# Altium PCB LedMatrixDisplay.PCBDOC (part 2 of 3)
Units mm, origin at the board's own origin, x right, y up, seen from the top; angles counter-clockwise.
Board outline 305.05 x 54.1 mm, 4 copper layers (Top Layer, POWER, GROUND, Bottom Layer); 103 components, 165 nets, 805 pads, 317 vias.
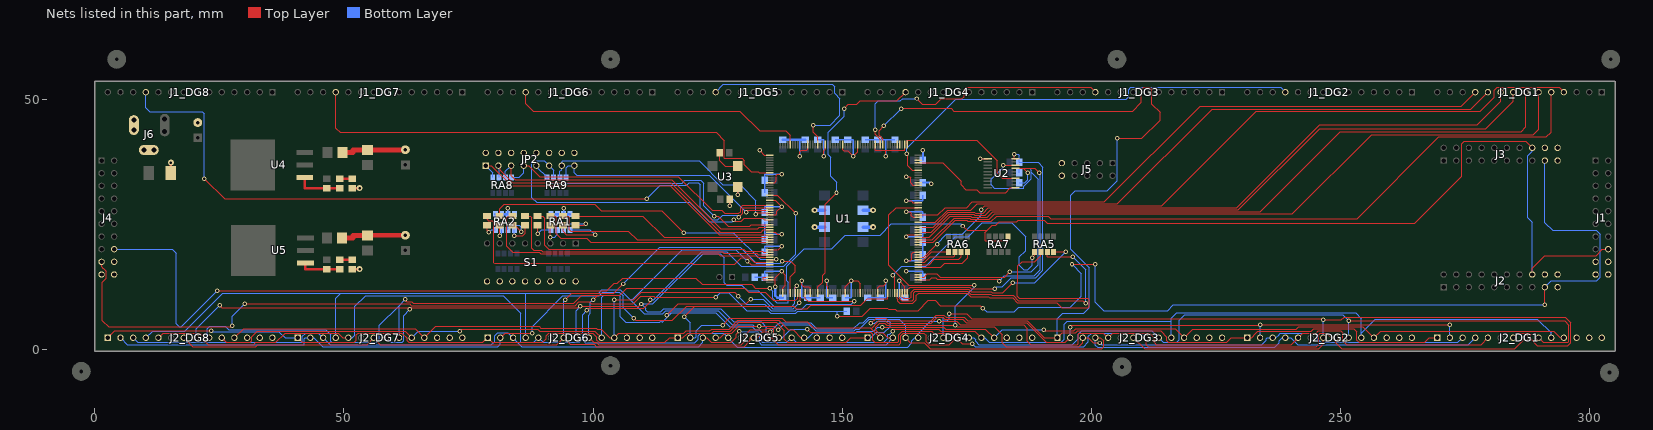
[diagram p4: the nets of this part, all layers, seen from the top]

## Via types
v1: diameter 0.9, hole 0.5, Top Layer to Bottom Layer, 307 vias
v2: diameter 1.2, hole 0.5, Top Layer to Bottom Layer, 9 vias
v3: diameter 1.27, hole 0.711, Top Layer to Bottom Layer, 1 vias

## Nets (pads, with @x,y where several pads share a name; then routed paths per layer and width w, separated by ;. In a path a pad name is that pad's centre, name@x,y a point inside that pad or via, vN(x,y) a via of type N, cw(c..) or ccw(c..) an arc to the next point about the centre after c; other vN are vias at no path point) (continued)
CNT16: J1.16 J2.16 J3.16 J4.16 RA7.1 | length 382.3
  Top Layer w0.2: v1(24.588,11.684) 102.718,11.684 104.242,13.208 104.902,13.208 105.969,14.275 120.65,14.275 121.92,13.005 131.826,13.005 132.309,12.522 132.309,12.446 132.512,12.243 v1(135.459,12.243) ; v1(174.219,24.714) 175.057,23.876 179.096,23.876 ; RA7.1@183.262,22.657 183.262,21.996 183.008,21.742 178.639,21.742 178.639,23.317 178.588,23.368 180.061,24.841 180.798,24.841 181.509,25.552 184.989,25.552 185.319,25.883 190.475,25.883 191.085,25.273 264.872,25.273 274.32,34.722 274.32,41.25 274.803,41.732 287.071,41.732 J3.16@288.417,40.386 ; J2.16@288.417,14.986 288.417,16.256 290.957,18.796 301.219,18.796 302.387,19.964 302.387,20.066 J1.16@303.657,20.066
  Bottom Layer w0.2: J4.16@3.937,20.066 15.571,20.066 16.383,19.253 16.383,5.105 16.968,4.521 17.425,4.521 v1(24.588,11.684) ; v1(135.459,12.243) 136.043,11.659 136.043,10.211 136.906,9.347 139.142,9.347 139.142,13.462 138.837,13.767 138.837,16.662 142.342,20.168 147.879,20.168 150.597,22.885 157.582,22.885 159.817,25.121 173.813,25.121 v1(174.219,24.714) ; J2.16@288.417,14.986 288.417,25.476 287.478,26.416 287.478,38.786 288.417,39.726 J3.16@288.417,40.386
CNT17: J2.17 J3.17 J4.17 R12.2 | length 382.4
  Top Layer w0.2: J4.17@1.397,17.526 1.397,16.51 1.651,16.256 1.702,16.256 2.337,15.621 2.337,14.224 1.575,13.462 1.575,5.74 2.845,4.47 27.432,4.47 v1(27.661,4.699) ; v1(30.125,9.093) 63.221,9.093 63.551,8.763 96.419,8.763 97.13,9.474 99.264,9.474 99.594,9.144 108.077,9.144 109.601,10.668 112.141,10.668 112.395,10.414 v1(124.587,10.414) ; v1(148.971,6.604) 153.999,6.604 155.65,8.255 159.073,8.255 159.327,8.001 160.655,8.001 160.909,7.747 165.227,7.747 167.259,9.779 168.656,9.779 169.672,8.763 177.673,8.763 v1(178.181,8.255) ; v1(196.088,17.018) v1(200.787,17.018) ; v1(290.957,8.89) J2.17@290.957,12.446
  Bottom Layer w0.2: v1(27.661,4.699) 27.661,6.629 v1(30.125,9.093) ; v1(124.587,10.414) 125.476,11.303 127.254,11.303 130.81,7.747 135.103,7.747 135.611,7.239 140.64,7.239 141.021,7.62 R12.2@150.942,7.62 ; v1(148.971,6.604) 148.971,7.62 ; v1(178.181,8.255) 178.943,7.493 184.531,7.493 185.42,8.382 195.707,8.382 197.993,10.668 197.993,15.113 v1(196.088,17.018) ; v1(200.787,17.018) 200.787,9.398 202.438,7.747 215.265,7.747 216.408,8.89 v1(290.957,8.89) ; J2.17@290.957,12.446 292.227,13.716 301.371,13.716 302.057,14.402 302.057,23.038 301.219,23.876 292.481,23.876 290.957,25.4 J3.17@290.957,37.846
DATA0: RA5.5 U1.99 | length 48.5
  Top Layer w0.2: v1(160.097,14.808) 160.577,14.327 U1.99@160.577,11.273 ; v1(188.113,18.351) 188.596,18.834 RA5.5@188.596,19.507
  Bottom Layer w0.2: v1(160.097,14.808) 161.951,16.662 166.726,16.662 172.67,22.606 175.286,22.606 178.08,25.4 183.961,25.4 186.767,22.594 186.767,19.768 185.497,18.498 185.497,16.815 186.411,15.9 187.212,15.9 188.113,16.801 v1(188.113,18.351)
DATA1: RA5.6 U1.100 | length 71.4
  Top Layer w0.2: U1.100@161.077,11.273 161.077,10.135 161.163,10.049 161.163,9.601 161.519,9.246 164.186,9.246 164.846,9.906 164.846,10.795 165.303,11.252 175.036,11.252 175.747,10.541 179.324,10.541 179.578,10.287 184.194,10.287 185.134,9.347 193.015,9.347 194.031,8.331 199.34,8.331 199.594,8.585 199.594,9.804 199.213,10.185 185.522,10.185 185.09,10.617 185.09,13.056 185.217,13.183 185.217,16.713 186.081,17.577 188.646,17.577 189.866,18.796 RA5.6@189.866,19.507
DATA2: RA5.7 U1.101 | length 57.6
  Top Layer w0.2: U1.101@161.577,11.273 161.577,10.084 161.933,9.728 164.008,9.728 164.338,10.058 164.338,11.303 164.687,11.652 175.202,11.652 175.805,11.049 179.8,11.049 180.054,10.795 184.252,10.795 185.293,9.754 198.247,9.754 v1(198.832,9.169) ; RA5.7@191.136,19.507 191.136,18.593 v1(196.215,18.593)
  Bottom Layer w0.2: v1(196.215,18.593) 198.832,15.977 v1(198.832,9.169)
DATA3: RA5.8 U1.102 | length 41.1
  Top Layer w0.2: U1.102@162.077,11.273 162.077,10.414 162.306,10.185 163.551,10.185 163.803,10.438 163.803,11.403 164.452,12.052 175.367,12.052 175.863,11.557 179.858,11.557 180.086,11.328 182.195,11.328 v1(184.176,13.31) ; RA5.8@192.406,19.507 v1(194.818,19.507)
  Bottom Layer w0.2: v1(184.176,13.31) 188.621,13.31 v1(194.818,19.507)
DATA4: RA6.5 U1.114 | length 6.8
  Top Layer w0.2: U1.114@165.227,17.923 166.387,17.923 167.971,19.507 RA6.5@171.324,19.507
DATA5: RA6.6 U1.113 | length 8.7
  Top Layer w0.2: U1.113@165.227,17.423 166.522,17.423 167.64,18.542 172.391,18.542 172.594,18.745 RA6.6@172.594,19.507
DATA6: RA6.7 U1.112 | length 10.3
  Top Layer w0.2: U1.112@165.227,16.923 167.412,16.923 168.497,18.009 173.33,18.009 173.864,18.542 RA6.7@173.864,19.507
DATA7: RA6.8 U1.111 | length 11.9
  Top Layer w0.2: U1.111@165.227,16.423 169.749,16.423 170.597,17.272 174.067,17.272 175.134,18.339 RA6.8@175.134,19.507
DIN: U1.153 U2.1 | length 22.8
  Top Layer w0.2: U1.153@165.227,37.423 170.12,37.423 173.845,33.699 173.845,32.969 174.785,32.029 177.013,32.029 177.623,31.42 182.753,31.42 183.711,32.377 U2.1@184.758,32.377
DONE: R4.2 U1.104 U2.10 | length 59.2
  Top Layer w0.2: U1.104@163.077,11.273 163.077,11.938 163.592,12.452 175.533,12.452 175.895,12.09 v1(180.62,12.09) ; v1(184.481,39.065) 184.481,38.227 U2.10@184.758,38.227
  Bottom Layer w0.2: v1(180.62,12.09) 181.026,12.497 182.068,12.497 183.896,14.326 188.773,14.326 190.246,15.799 190.246,36.525 189.307,37.465 R4.2@185.481,37.465 185.481,38.862 185.278,39.065 v1(184.481,39.065)
ENABLE0: J1_DG1.11 U1.132 | length 122
  Top Layer w0.2: U1.132@165.227,26.923 169.164,26.923 170.638,28.397 174.93,28.397 176.073,29.54 202.565,29.54 221.793,48.768 274.193,48.768 J1_DG1.11@276.987,51.562
ENABLE1: J1_DG2.11 U1.150 | length 88.3
  Top Layer w0.2: v1(162.941,39.218) 163.17,38.989 163.17,36.805 164.051,35.923 U1.150@165.227,35.923
  Bottom Layer w0.2: v1(162.941,39.218) 162.941,40.335 172.797,50.19 207.01,50.19 207.468,50.648 207.468,52.07 207.899,52.502 237.948,52.502 J1_DG2.11@238.887,51.562
ENABLE2: J1_DG3.11 U1.168 | length 56.3
  Top Layer w0.2: v1(156.591,44.018) 156.591,43.15 157.577,42.164 U1.168@157.577,41.073 ; v1(164.897,50.292) 166.091,49.098 168.733,49.098 169.85,50.216 174.016,50.216 174.448,50.648 174.448,52.07 174.879,52.502 199.848,52.502 J1_DG3.11@200.787,51.562
  Bottom Layer w0.2: v1(156.591,44.018) 156.591,49.251 157.201,49.86 161.671,49.86 162.103,50.292 v1(164.897,50.292)
ENABLE3: J1_DG4.11 U1.68 | length 54.2
  Top Layer w0.2: U1.68@145.077,11.273 145.077,12.489 146.05,13.462 146.05,14.859 146.558,15.367 146.558,29.083 v1(148.844,31.369) ; v1(150.368,48.26) 151.206,49.098 152.908,49.098 153.645,49.835 160.96,49.835 J1_DG4.11@162.687,51.562
  Bottom Layer w0.2: v1(148.844,31.369) 148.844,33.528 147.701,34.671 147.701,38.481 147.193,38.989 147.193,43.561 150.368,46.736 v1(150.368,48.26)
ENABLE4: J1_DG5.11 U1.193 | length 41.3
  Top Layer w0.2: v1(144.145,44.958) 144.145,43.561 145.077,42.629 U1.193@145.077,41.073
  Bottom Layer w0.2: J1_DG5.11@124.587,51.562 126.137,53.111 148.006,53.111 148.463,52.654 148.463,51.308 149.505,50.267 149.505,46.889 147.574,44.958 v1(144.145,44.958)
ENABLE5: J1_DG6.11 U1.204 | length 59.9
  Top Layer w0.2: J1_DG6.11@86.487,51.562 86.487,49.225 87.961,47.752 129.464,47.752 133.408,43.808 138.695,43.808 139.577,42.926 U1.204@139.577,41.073
ENABLE6: J1_DG7.11 U1.8 | length 100.5
  Top Layer w0.2: J1_DG7.11@48.387,51.562 48.387,44.348 49.251,43.485 124.74,43.485 126.365,41.859 126.365,38.303 129.896,38.303 130.353,37.846 130.353,37.008 131.75,35.611 133.188,35.611 133.376,35.423 U1.8@135.427,35.423
ENABLE7: J1_DG8.11 U1.22 | length 152.5
  Top Layer w0.2: v1(22.022,34.214) 26.086,30.15 110.77,30.15 v1(110.821,30.201) ; v1(129.236,26.467) 129.998,27.229 129.998,28.27 130.151,28.423 U1.22@135.427,28.423
  Bottom Layer w0.2: J1_DG8.11@10.287,51.562 10.287,48.412 11.1,47.6 21.616,47.6 22.022,47.193 v1(22.022,34.214) ; v1(110.821,30.201) 113.462,32.842 118.771,32.842 119.304,33.376 121.108,33.376 121.514,32.969 121.514,28.372 123.952,25.933 125.07,25.933 125.984,26.848 128.855,26.848 v1(129.236,26.467)
FPGA_C\S\: U1.160
FPGA_D1: U1.145
FPGA_D4: U1.126
FPGA_D5: U1.120
FPGA_D6: U1.116
FPGA_D7: U1.108
"FPGA_DOUT_ BUSY": U1.154
FPGA_TDO-TDI: U1.157 U2.4 | length 27.2
  Top Layer w0.2: U1.157@163.077,41.073 163.077,41.961 176.962,41.961 181.077,37.846 181.077,35.394 182.144,34.327 U2.4@184.758,34.327
FPGA_W\R\I\T\E\: U1.161
GND: C1.2 C2.2 C3.2 C4.2 C5.1 C6.1 C7.1 C8.1 C9.1 C10.1 C11.1 C12.1 C13.1 C14.1 C15.1 C16.1 C17.1 C18.1 C19.2 C20.2 C21.2 C22.2 C23.2 C24.2 C25.2 C26.2 C27.2 C28.2 C29.2 C30.2 C31.2 C32.2 C34.1 C35.1 C36.1 C37.2 C38.2 C39.2 C40.2 C41.2 C42.2 C43.2 C44.2 D1.1 J1.17 J1.18 J1.19 J1.20 J2.18 J2.19 J2.20 J2_DG1.12 J2_DG1.13 J2_DG1.14 J2_DG2.12 J2_DG2.13 J2_DG2.14 J2_DG3.12 J2_DG3.13 J2_DG3.14 J2_DG4.12 J2_DG4.13 J2_DG4.14 J2_DG5.12 J2_DG5.13 J2_DG5.14 J2_DG6.12 J2_DG6.13 J2_DG6.14 J2_DG7.12 J2_DG7.13 J2_DG7.14 J2_DG8.12 J2_DG8.13 J2_DG8.14 J3.18 J3.19 J3.20 J4.18 J4.19 J4.20 J5.9 J5.10 J6.2 J6.2A J6.2B J6.3 J6.3A J6.3B JP2.2 JP2.4 JP2.6 JP2.8 JP2.10 JP2.12 JP2.14 JP2.16 R1.1 R9.1 R11.2 RA1.5 RA1.6 RA1.7 RA1.8 RA2.5 RA2.6 RA2.7 RA2.8 S1.9 S1.10 S1.11 S1.12 S1.13 S1.14 S1.15 S1.16 U1.1 U1.12 U1.19 U1.25 U1.32 U1.39 U1.50 U1.51 U1.54 U1.65 U1.72 U1.79 U1.85 U1.92 U1.103 U1.117 U1.124 U1.131 U1.137 U1.144 U1.158 U1.170 U1.177 U1.183 U1.190 U1.197 U2.11 U3.2 | length 260.8
  Top Layer w0.2: v1(133.411,39.878) 134.366,38.923 U1.1@135.427,38.923 ; U1.50@135.427,14.423 134.112,14.423 134.112,13.923 U1.51@135.427,13.923 136.479,13.923 136.602,14.046 ; U1.39@135.427,19.923 137.158,19.923 v1(137.84,20.606) ; U1.32@135.427,23.423 136.597,23.423 136.914,23.106 v1(137.84,23.106) ; U1.25@135.427,26.923 136.652,26.923 136.906,27.178 136.906,27.672 v1(137.84,28.606) 136.523,29.923 U1.19@135.427,29.923 ; U1.12@135.427,33.423 136.421,33.423 136.779,33.782 136.779,34.925 136.96,35.106 v1(137.84,35.106) ; v1(136.602,12.497) 136.602,14.046 ; 137.5,15.265 136.602,14.367 136.602,14.046 ; v1(137.84,15.606) 138.608,14.838 138.608,12.802 138.077,12.271 U1.54@138.077,11.273 ; v1(141.439,38.674) 141.439,39.584 141.732,39.878 142.875,39.878 143.077,40.08 U1.197@143.077,41.073 ; v1(141.895,13.686) 141.895,12.919 142.24,12.573 143.383,12.573 143.577,12.379 U1.65@143.577,11.273 ; v1(146.26,38.66) 146.26,39.834 146.577,40.151 U1.190@146.577,41.073 ; v1(146.895,13.686) 146.895,12.745 147.077,12.562 U1.72@147.077,11.273 ; U1.183@150.077,41.073 150.077,40.042 150.338,39.781 151.079,39.781 v1(152.186,38.674) 153.077,39.565 U1.177@153.077,41.073 ; U1.79@150.577,11.273 150.577,12.504 v1(151.76,13.686) 153.065,13.686 153.577,13.174 U1.85@153.577,11.273 ; U1.170@156.577,41.073 156.577,39.878 158.75,39.878 ; U1.92@157.077,11.273 157.077,12.297 157.48,12.7 158.369,12.7 158.75,13.081 v1(158.75,13.718) ; v1(158.75,38.66) 158.75,39.878 ; v1(161.395,13.686) 162.577,12.504 U1.103@162.577,11.273 ; U1.158@162.577,41.073 162.577,39.878 158.75,39.878 ; v1(162.814,17.741) 163.664,17.741 163.957,18.034 163.957,19.177 164.204,19.423 U1.117@165.227,19.423 ; v1(162.814,22.606) 163.132,22.923 U1.124@165.227,22.923 ; v1(162.814,27.606) 163.529,27.606 163.83,27.305 163.83,26.797 164.204,26.423 U1.131@165.227,26.423 ; v1(162.814,29.741) 163.808,29.741 164.125,29.423 U1.137@165.227,29.423 ; v1(162.814,34.606) 163.514,34.606 163.703,34.417 163.703,33.401 164.181,32.923 U1.144@165.227,32.923 ; v1(177.673,38.227) U2.11@179.208,38.227
  Top Layer w0.3: v1(127.442,28.772) C37.2@127.442,30.099 ; v1(129.032,30.954) U3.2@129.032,32.531
  Top Layer w0.5: D1.1@15.304,35.306 v2(15.304,37.43) ; R11.2@51.689,16.068 v2(53.166,16.068) ; R9.1@51.689,32.324 v2(53.166,32.324) ; C42.2@62.206,40.005 C42.2@62.23,39.981 ; C44.2@62.357,22.812 C44.2@62.357,22.86
  Top Layer w1: C40.2@49.609,22.352 51.816,22.352 51.816,22.812 C41.2@54.737,22.812 54.737,22.86 C44.2@62.357,22.86 ; C38.2@49.76,39.497 51.816,39.497 51.816,39.957 C39.2@54.737,39.957 62.357,39.957 C42.2@62.357,40.005
  Bottom Layer w0.254: RA2.7@82.931,27.102 v1(82.931,28.279) ; RA1.7@94.107,27.102 v1(94.107,28.279)
  Bottom Layer w0.3: R1.1@132.445,14.423 C34.1@134.477,14.423 134.477,15.606 v1(137.84,15.606) ; C22.2@134.477,19.423 134.477,20.606 v1(137.84,20.606) ; C29.2@134.477,21.923 134.477,23.106 v1(137.84,23.106) ; C28.2@134.477,25.423 134.493,23.114 ; C21.2@134.477,27.423 134.477,28.606 v1(137.84,28.606) ; C27.2@134.477,31.423 C20.2@134.477,33.923 134.477,35.106 v1(137.84,35.106) ; v1(141.439,38.674) 141.439,42.023 ; v1(141.895,13.686) 141.895,10.323 C25.2@143.077,10.323 C32.2@145.577,10.323 ; C7.1@142.577,42.037 C7.1@142.621,42.037 ; C15.1@145.077,42.023 146.26,42.023 v1(146.26,38.66) ; v1(146.895,13.686) 146.895,10.323 C35.1@148.077,10.323 ; C14.1@148.577,42.023 C6.1@151.077,42.023 ; C24.2@150.577,10.323 151.76,10.323 v1(151.76,13.686) ; C6.1@151.003,42.037 151.077,42.037 152.186,42.037 v1(152.186,38.674) ; C13.1@154.577,42.023 C5.1@157.077,42.023 158.75,42.023 ; C31.2@155.077,10.323 C23.2@157.577,10.323 157.567,10.355 157.577,10.355 158.75,10.355 v1(158.75,13.718) ; v1(158.75,38.66) 158.75,42.023 ; C9.1@160.577,42.023 158.75,42.023 ; v1(161.395,13.686) 161.395,10.323 C36.1@162.577,10.323 ; v1(162.814,15.606) 166.177,15.606 C19.2@166.177,14.423 ; v1(162.814,17.741) 166.177,17.741 C12.1@166.177,18.923 C18.1@166.177,21.423 ; v1(162.814,22.606) 166.177,22.606 C17.1@166.177,23.923 ; v1(162.814,27.606) 166.177,27.606 C11.1@166.177,26.423 ; v1(162.814,29.741) 166.177,29.741 C16.1@166.177,30.923
  Bottom Layer w0.4: C10.1@166.177,33.423 167.618,33.423 v1(167.894,33.147) ; C30.2@166.177,37.923 v1(166.177,39.878)
  Bottom Layer w0.5: RA2.5@80.391,27.102 RA2.6@81.661,27.102 RA2.7@82.931,27.102 RA2.8@84.201,27.102 ; RA1.5@91.567,27.102 RA1.6@92.837,27.102 RA1.7@94.107,27.102 RA1.8@95.377,27.102 ; v1(136.602,12.497) 136.602,10.718 136.997,10.323 C26.2@138.077,10.323 ; C8.1@138.077,42.023 141.439,42.023 C7.1@142.577,42.023
  Bottom Layer w0.7: v2(144.444,24.473) C3.2@146.477,24.473 ; v2(144.444,27.873) C2.2@146.477,27.873 ; C4.2@154.177,24.473 v2(156.21,24.473) ; C1.2@154.177,27.873 v2(156.21,27.873)
GREEN0: J2_DG1.1 J2_DG2.1 J2_DG3.1 J2_DG4.1 J2_DG5.1 J2_DG6.1 J2_DG7.1 J2_DG8.1 U1.167 | length 431.6
  Top Layer w0.2: J2_DG8.1@2.667,2.286 4.039,3.658 v1(23.419,3.658) ; J2_DG7.1@40.767,2.286 41.707,1.346 52.096,1.346 52.528,1.778 52.528,2.896 52.858,3.226 61.646,3.226 62.688,2.184 62.688,1.676 63.018,1.346 77.928,1.346 J2_DG6.1@78.867,2.286 79.807,1.346 89.891,1.346 90.628,2.083 90.628,2.743 91.11,3.226 99.949,3.226 100.788,2.388 100.788,1.829 101.27,1.346 114.427,1.346 115.367,2.286 J2_DG5.1@116.967,2.286 118.034,2.286 118.974,3.226 123.851,3.226 124.257,3.632 127.508,3.632 129.25,5.373 136.74,5.373 138.405,3.708 138.405,2.007 139.065,1.346 150.8,1.346 151.74,2.286 J2_DG4.1@155.067,2.286 ; v1(155.728,5.182) 156.769,6.223 158.75,6.223 159.258,5.715 167.811,5.715 168.903,6.807 170.383,6.807 170.815,6.375 174.473,6.375 175.159,5.69 187.154,5.69 190.558,2.286 J2_DG3.1@193.167,2.286 194.158,3.277 196.876,3.277 197.257,3.658 213.843,3.658 215.088,2.413 215.088,1.676 215.418,1.346 227.127,1.346 228.067,2.286 J2_DG2.1@231.267,2.286 232.131,2.286 232.537,2.692 232.537,2.819 233.35,3.632 244.094,3.632 244.552,4.089 252.629,4.089 253.188,3.531 253.188,1.829 253.67,1.346 266.827,1.346 267.767,2.286 J2_DG1.1@269.367,2.286 ; U1.167@158.077,41.073 158.077,42.266 157.404,42.939 157.404,43.815 v1(158.369,44.78) ; v1(161.798,48.209) 161.882,48.292 171.817,48.292 172.358,47.752 208.23,47.752 210.008,49.53 210.008,52.07 210.439,52.502 211.659,52.502 212.09,52.07 212.09,49.174 213.741,47.523 213.741,45.974 210.084,42.316 v1(205.156,42.316)
  Bottom Layer w0.2: v1(23.419,3.658) 23.546,3.531 36.983,3.531 38.227,2.286 J2_DG7.1@40.767,2.286 ; J2_DG4.1@155.067,2.286 155.728,2.286 156.795,3.353 158.471,3.353 159.639,4.521 159.639,5.334 159.385,5.588 156.972,5.588 156.566,5.182 v1(155.728,5.182) ; v1(158.369,44.78) v1(161.798,48.209) ; J2_DG3.1@193.167,2.286 193.167,6.147 194.183,7.163 198.4,7.163 199.594,8.357 199.594,16.358 195.86,20.091 195.86,30.836 196.774,31.75 203.124,31.75 205.156,33.782 v1(205.156,42.316)
GREEN1: J2_DG1.2 J2_DG2.2 J2_DG3.2 J2_DG4.2 J2_DG5.2 J2_DG6.2 J2_DG7.2 J2_DG8.2 U1.96 | length 346.9
  Top Layer w0.2: J2_DG6.2@81.407,2.286 82.347,3.226 v1(87.783,3.226) ; v1(108.128,6.172) 108.535,5.766 115.926,5.766 118.771,8.611 140.234,8.611 140.767,8.077 143.002,8.077 143.714,8.788 153.695,8.788 155.013,10.106 159.077,10.106 U1.96@159.077,11.273 ; v1(118.314,6.502) 120.422,8.611 ; v1(125.984,4.801) 127.357,6.173 137.999,6.173 138.686,5.486 143.002,5.486 144.221,4.267 155.626,4.267 J2_DG4.2@157.607,2.286 ; 155.769,4.124 155.769,4.131 157.353,5.715 158.623,5.715 159.112,5.226 167.888,5.226 169.037,6.375 170.155,6.375 170.561,5.969 174.219,5.969 174.905,5.283 186.97,5.283 190.907,1.346 194.768,1.346 J2_DG3.2@195.707,2.286 ; v1(195.707,4.445) 196.114,4.851 233.757,4.851 v1(233.807,4.902) v1(271.907,4.902)
  Bottom Layer w0.2: J2_DG8.2@5.207,2.286 6.554,0.94 42.114,0.94 42.114,2.083 42.317,2.286 J2_DG7.2@43.307,2.286 43.968,2.286 45.771,0.483 80.874,0.483 81.407,1.016 J2_DG6.2@81.407,2.286 ; v1(87.783,3.226) 87.783,4.521 93.955,10.693 101.244,10.693 101.981,11.43 105.283,11.43 106.02,10.693 106.02,8.28 v1(108.128,6.172) ; v1(118.314,6.502) 119.507,5.309 J2_DG5.2@119.507,2.286 120.473,2.286 120.676,2.489 120.676,3.708 121.768,4.801 v1(125.984,4.801) ; J2_DG3.2@195.707,2.286 v1(195.707,4.445) ; J2_DG2.2@233.807,2.286 v1(233.807,4.902) ; J2_DG1.2@271.907,2.286 v1(271.907,4.902)
GREEN2: J2_DG1.3 J2_DG2.3 J2_DG3.3 J2_DG4.3 J2_DG5.3 J2_DG6.3 J2_DG7.3 J2_DG8.3 U1.135 | length 339.2
  Top Layer w0.2: J2_DG5.3@122.047,2.286 122.809,2.286 123.749,1.346 127.686,1.346 128.728,2.388 128.728,2.997 v1(129.286,3.556) ; J2_DG4.3@160.147,2.286 159.131,2.286 158.115,3.302 157.226,3.302 156.718,3.81 156.718,4.445 157.48,5.207 158.496,5.207 158.877,4.826 172.619,4.826 172.974,4.47 180.518,4.47 182.068,2.921 182.068,1.27 182.88,0.457 197.435,0.457 198.247,1.27 J2_DG3.3@198.247,2.286 199.314,2.286 200.356,1.245 v1(201.676,1.245) ; U1.135@165.227,28.423 160.834,28.423 159.335,26.924 159.335,16.84 163.322,12.852 v1(176.454,12.852)
  Bottom Layer w0.2: J2_DG8.3@7.747,2.286 8.687,1.346 41.707,1.346 41.707,2.591 42.342,3.226 44.908,3.226 47.244,0.889 79.629,0.889 80.264,1.524 80.264,2.667 80.899,3.302 82.931,3.302 85.7,0.533 121.184,0.533 122.047,1.397 J2_DG5.3@122.047,2.286 ; v1(129.286,3.556) 129.388,3.454 133.071,3.454 133.401,3.124 133.401,1.27 133.731,0.94 158.801,0.94 J2_DG4.3@160.147,2.286 ; v1(172.644,4.801) 172.644,8.636 176.454,12.446 v1(176.454,12.852) ; v1(201.676,1.245) 202.032,0.889 234.163,0.889 235.077,1.803 235.077,2.083 235.281,2.286 J2_DG2.3@236.347,2.286 237.008,2.286 237.617,2.896 237.617,3.023 237.821,3.226 244.907,3.226 245.237,2.896 245.237,2.057 245.949,1.346 273.508,1.346 J2_DG1.3@274.447,2.286
GREEN3: J2_DG1.4 J2_DG2.4 J2_DG3.4 J2_DG4.4 J2_DG5.4 J2_DG6.4 J2_DG7.4 J2_DG8.4 U1.45 | length 350.6
  Top Layer w0.2: J2_DG5.4@124.587,2.286 125.527,2.286 126.467,3.226 127.813,3.226 129.21,4.623 136.398,4.623 v1(137.135,3.886) ; v1(130.988,17.628) 131.692,16.923 U1.45@135.427,16.923 ; J2_DG4.4@162.687,2.286 163.653,1.321 166.421,1.321 167.691,0.051 202.032,0.051 202.438,0.457 202.438,1.651 201.803,2.286 J2_DG3.4@200.787,2.286
  Bottom Layer w0.2: J2_DG8.4@10.287,2.286 11.634,3.632 18.111,3.632 25.731,11.252 101.124,11.252 101.785,11.913 105.436,11.913 110.262,7.087 113.97,7.087 114.58,7.696 125.146,7.696 127.889,4.953 132.011,4.953 132.341,4.623 v1(133.3,4.623) ; J2_DG7.4@48.387,2.286 48.387,10.211 49.429,11.252 ; J2_DG6.4@86.487,2.286 86.487,11.252 ; 107.341,10.008 107.976,10.008 117.933,19.964 128.651,19.964 v1(130.988,17.628) ; v1(137.135,3.886) 138.202,4.953 143.383,4.953 144.634,3.702 152.419,3.702 152.673,3.956 153.41,3.956 154.942,5.488 155.448,5.994 161.443,5.994 162.687,4.75 J2_DG4.4@162.687,2.286 ; J2_DG3.4@200.787,2.286 200.787,0.838 201.245,0.381 236.728,0.381 237.617,1.27 237.617,1.676 238.227,2.286 J2_DG2.4@238.887,2.286 239.954,2.286 241.377,0.864 275.565,0.864 J2_DG1.4@276.987,2.286
GREEN4: J2_DG1.5 J2_DG2.5 J2_DG3.5 J2_DG4.5 J2_DG5.5 J2_DG6.5 J2_DG7.5 J2_DG8.5 U1.17 | length 372.3
  Top Layer w0.2: J2_DG8.5@12.827,2.286 13.767,3.226 21.209,3.226 22.048,2.388 22.048,1.676 22.784,0.94 31.954,0.94 32.36,1.346 36.399,1.346 38.278,3.226 48.845,3.226 49.784,2.286 J2_DG7.5@50.927,2.286 ; v1(98.73,7.772) 99.137,8.179 110.135,8.179 111.456,9.5 v1(111.456,9.881) ; U1.17@135.427,30.923 136.971,30.923 v1(140.64,27.254) ; v1@169.418,5.563 172.949,5.563 173.635,4.877 186.36,4.877 187.148,4.089 187.148,1.575 187.833,0.889 197.13,0.889 197.308,1.067 197.308,2.946 197.587,3.226 202.388,3.226 J2_DG3.5@203.327,2.286 204.267,3.226 211.659,3.226 212.548,2.337 212.548,1.397 213.03,0.914 240.056,0.914 242.367,3.226 245.085,3.226 245.517,3.658 250.038,3.658 250.419,3.277 250.419,1.727 251.232,0.914 278.156,0.914 J2_DG1.5@279.527,2.286
  Bottom Layer w0.2: J2_DG7.5@50.927,2.286 51.689,2.286 52.197,2.794 52.197,8.585 54.356,10.744 81.992,10.744 85.548,7.188 85.548,1.422 85.624,1.346 88.088,1.346 J2_DG6.5@89.027,2.286 89.967,1.346 97.206,1.346 97.917,2.057 97.917,6.96 v1(98.73,7.772) ; 97.79,1.93 98.425,1.295 120.371,1.295 121.082,2.007 121.082,2.718 121.59,3.226 126.188,3.226 128.982,0.432 163.119,0.432 163.957,1.27 163.957,1.676 164.567,2.286 J2_DG4.5@165.227,2.286 165.227,3.124 167.691,5.588 v1(169.418,5.588) ; v1(111.456,9.881) 112.167,9.881 121.844,19.558 126.873,19.558 129.744,16.688 138.278,16.688 140.64,19.05 v1(140.64,27.254)
INIT: R3.2 U1.107 U2.8 | length 66.8
  Top Layer w0.2: U1.107@165.227,14.423 166.421,14.423 167.085,15.088 168.987,15.088 169.647,14.427 182.576,14.427 v1(183.642,15.494) ; v1(182.271,36.927) U2.8@184.758,36.927
  Bottom Layer w0.2: v1(182.271,36.927) 182.271,36.474 179.858,34.061 179.858,32.969 180.493,32.334 186.436,32.334 186.436,32.664 187.96,34.188 187.96,35.458 ; v1(183.642,15.494) 187.91,15.494 189.357,16.942 189.357,34.061 187.96,35.458 ; R3.2@185.481,35.433 185.481,36.271 187.63,36.271 187.96,35.941 187.96,35.458
JUMPERS0: JP2.1 RA8.1 U1.33 | length 65.6
  Top Layer w0.2: JP2.1@78.487,36.83 79.604,36.83 83.693,32.741 115.469,32.741 125.286,22.923 U1.33@135.427,22.923
  Bottom Layer w0.2: JP2.1@78.487,36.83 79.883,35.433 RA8.1@79.883,34.468
JUMPERS1: JP2.3 RA8.2 U1.31 | length 63.1
  Top Layer w0.2: JP2.3@81.027,36.83 81.382,36.83 81.382,35.89 83.897,33.376 115.621,33.376 125.502,23.495 133.709,23.495 134.138,23.923 U1.31@135.427,23.923
  Bottom Layer w0.2: JP2.3@81.027,36.83 81.153,36.83 RA8.2@81.153,34.468
JUMPERS2: JP2.5 RA8.3 U1.30 | length 61.2
  Top Layer w0.2: JP2.5@83.567,36.83 83.567,34.823 84.379,34.011 115.748,34.011 125.603,24.155 133.057,24.155 133.325,24.423 U1.30@135.427,24.423
  Bottom Layer w0.2: RA8.3@82.423,34.468 82.423,35.687 JP2.5@83.567,36.83
JUMPERS3: JP2.7 RA8.4 U1.21 | length 58.7
  Top Layer w0.2: JP2.7@86.107,36.83 87.097,36.83 89.307,34.62 117.145,34.62 123.902,27.864 125.807,27.864 126.442,27.229 129.21,27.229 129.591,27.61 129.591,28.499 130.016,28.923 U1.21@135.427,28.923
  Bottom Layer w0.2: RA8.4@83.693,34.468 85.167,34.468 86.107,35.408 JP2.7@86.107,36.83
JUMPERS4: JP2.9 RA9.1 U1.29 | length 55.6
  Top Layer w0.2: v1(124.283,26.695) 125.121,26.695 127.153,24.663 131.465,24.663 131.725,24.923 U1.29@135.427,24.923
  Bottom Layer w0.2: JP2.9@88.647,36.83 88.647,36.626 RA9.1@90.805,34.468 90.805,33.782 91.263,33.325 117.856,33.325 118.44,33.909 121.59,33.909 122.225,33.274 122.225,28.753 v1(124.283,26.695)
JUMPERS5: JP2.11 RA9.2 U1.27 | length 64.1
  Top Layer w0.2: v1(128.27,25.933) 128.524,25.679 129.718,25.679 130.302,26.264 134.036,26.264 134.376,25.923 U1.27@135.427,25.923
  Bottom Layer w0.2: RA9.2@92.075,34.468 92.075,35.941 90.247,37.77 88.037,37.77 87.707,37.44 87.707,30.404 88.672,29.439 119.355,29.439 123.267,25.527 127.94,25.527 v1@128.27,25.857
JUMPERS6: JP2.13 RA9.3 U1.24 | length 51.3
  Top Layer w0.2: v1(132.69,27.026) 133.088,27.423 U1.24@135.427,27.423
  Bottom Layer w0.2: RA9.3@93.345,34.468 93.345,35.662 93.727,36.043 JP2.13@93.727,36.83 93.727,37.541 93.955,37.77 121.285,37.77 126.035,33.02 129.49,33.02 132.69,29.82 v1(132.69,27.026)
JUMPERS7: JP2.15 RA9.4 U1.23 | length 47.8
  Top Layer w0.2: v1(130.76,27.508) 131.175,27.923 U1.23@135.427,27.923
  Bottom Layer w0.2: RA9.4@94.615,34.468 94.615,36.449 94.996,36.83 JP2.15@96.267,36.83 96.267,35.408 96.749,34.925 123.343,34.925 v1(130.76,27.508)
LED0: LED1.1 U1.35 | length 44.9
  Top Layer w0.2: LED1.1@93.98,26.721 95.022,26.721 95.276,26.467 95.276,24.003 95.581,23.698 107.061,23.698 108.836,21.923 U1.35@135.427,21.923
LED0#: LED1.2 RA1.1 | length 13.4
  Top Layer w0.2: LED1.2@93.98,24.821 93.98,23.622 94.666,22.936 v1(100.407,22.936)
  Bottom Layer w0.2: RA1.1@95.377,23.952 99.391,23.952 v1(100.407,22.936)
LED1: LED2.1 U1.34 | length 40.7
  Top Layer w0.2: LED2.1@96.52,26.721 109.978,26.721 114.275,22.423 U1.34@135.427,22.423
LED1#: LED2.2 RA1.2 | length 7.6
  Top Layer w0.2: LED2.2@96.52,24.821 98.176,24.821 v1(98.502,25.146)
  Bottom Layer w0.2: RA1.2@94.107,23.952 94.107,24.892 94.361,25.146 v1(98.502,25.146)
LED2: LED3.1 U1.36 | length 48.1
  Top Layer w0.2: LED3.1@91.44,26.721 92.38,26.721 92.634,26.467 92.634,23.139 93.549,22.225 98.781,22.225 99.583,21.423 U1.36@135.427,21.423
LED2#: LED3.2 RA1.3 | length 4.9
  Top Layer w0.2: v1(91.44,22.504) LED3.2@91.44,24.821
  Bottom Layer w0.2: v1(91.44,22.504) 92.329,22.504 92.837,23.012 RA1.3@92.837,23.952
LED3: LED4.1 U1.40 | length 52.7
  Top Layer w0.2: LED4.1@88.9,26.721 89.891,26.721 90.297,26.314 90.297,20.853 91.11,20.041 130.252,20.041 130.683,19.609 134.011,19.609 134.196,19.423 U1.40@135.427,19.423
LED3#: LED4.2 RA1.4 | length 4.7
  Top Layer w0.2: v1(88.9,23.114) LED4.2@88.9,24.821
  Bottom Layer w0.2: v1(88.9,23.114) 89.739,23.952 RA1.4@91.567,23.952
LED4: LED5.1 U1.41 | length 56
  Top Layer w0.2: LED5.1@86.36,26.721 87.453,26.721 87.681,26.492 87.681,20.218 88.062,19.837 89.586,19.837 89.866,19.558 125.883,19.558 126.238,19.202 132.893,19.202 133.172,18.923 U1.41@135.427,18.923
LED4#: LED5.2 RA2.1 | length 5.1
  Top Layer w0.2: v1(84.201,22.758) 85.903,22.758 86.36,23.216 LED5.2@86.36,24.821
  Bottom Layer w0.2: v1(84.201,22.758) RA2.1@84.201,23.952
LED5: LED6.1 U1.42 | length 60.7
  Top Layer w0.2: LED6.1@83.82,26.721 82.957,26.721 82.703,26.467 82.703,20.625 83.897,19.431 89.231,19.431 89.51,19.152 125.121,19.152 125.476,18.796 132.639,18.796 133.012,18.423 U1.42@135.427,18.423
LED5#: LED6.2 RA2.2 | length 6.9
  Top Layer w0.2: LED6.2@83.82,24.821 84.298,24.821 v1(85.598,23.52)
  Bottom Layer w0.2: RA2.2@82.931,23.952 82.931,24.638 83.16,24.867 85.167,24.867 85.598,24.435 v1(85.598,23.52)
LED6: LED7.1 U1.43 | length 63.4
  Top Layer w0.2: LED7.1@81.28,26.721 81.28,28.194 82.169,29.083 100.305,29.083 101.626,27.762 113.818,27.762 v1(118.212,23.368) ; U1.43@135.427,17.923 136.72,17.923 v1(136.805,18.009)
  Bottom Layer w0.2: v1(118.212,23.368) 128.169,23.368 133.528,18.009 v1(136.805,18.009)
LED6#: LED7.2 RA2.3 | length 3.4
  Top Layer w0.2: v1(81.28,22.758) LED7.2@81.28,24.821
  Bottom Layer w0.2: v1(81.28,22.758) 81.661,23.139 RA2.3@81.661,23.952
LED7: LED8.1 U1.44 | length 66.8
  Top Layer w0.2: LED8.1@78.74,26.721 78.74,26.06 79.02,25.781 79.756,25.781 80.087,25.451 80.087,17.374 80.239,17.221 119.863,17.221 120.041,17.043 128.423,17.043 129.769,18.39 131.369,18.39 132.335,17.423 U1.44@135.427,17.423
LED7#: LED8.2 RA2.4 | length 3.1
  Top Layer w0.2: LED8.2@78.74,24.821 78.74,23.8 v1(79.121,23.419)
  Bottom Layer w0.2: v1(79.121,23.419) 79.655,23.952 RA2.4@80.391,23.952
NetR5_1: R5.1 U3.3 | length 5.6
  Top Layer w0.2: R5.1@125.415,39.37 125.415,37.846 126.53,36.731 U3.3@129.032,36.731
NetR6_2: R6.2 R8.1 U4.1 | length 9.1
  Top Layer w0.5: U4.1@42.164,34.417 42.164,32.324 R6.2@46.609,32.324 R8.1@49.149,32.324
NetR7_2: R7.2 R10.1 U5.1 | length 8.1
  Top Layer w0.5: U5.1@42.291,17.272 42.291,16.068 R7.2@46.609,16.068 R10.1@49.149,16.068
NetR8_2: R8.2 R9.2 | length 2.5
  Top Layer w0.5: R8.2@49.149,34.224 R9.2@51.689,34.224
NetR10_2: R10.2 R11.1 | length 2.7
  Top Layer w0.5: R10.2@49.149,17.968 R11.1@51.689,17.968 R11.1@51.816,17.968
PROGRAM: R2.2 U1.106 U2.7 | length 55.2
  Top Layer w0.2: U1.106@165.227,13.923 167.543,13.923 167.996,14.376 168.707,14.376 169.063,14.021 181.102,14.021 v1(181.458,13.665) ; U2.7@184.758,36.277 186.304,36.277 ; v1(187.198,35.382) 186.304,36.277 ; v1(189.484,35.382) 188.59,36.277 186.304,36.277
  Bottom Layer w0.2: v1(181.458,13.665) 182.525,14.732 188.545,14.732 189.764,15.951 189.764,35.103 v1(189.484,35.382) ; R2.2@185.481,33.401 186.607,33.401 187.198,33.992 v1(187.198,35.382)
RED0: J2_DG1.7 J2_DG2.7 J2_DG3.7 J2_DG4.7 J2_DG5.7 J2_DG6.7 J2_DG7.7 J2_DG8.7 U1.57 | length 419.7
  Top Layer w0.2: J2_DG8.7@17.907,2.286 19.66,0.533 32.36,0.533 32.766,0.94 54.661,0.94 J2_DG7.7@56.007,2.286 57.354,0.94 92.761,0.94 J2_DG6.7@94.107,2.286 95.428,0.965 100.254,0.965 100.686,0.533 130.311,0.533 131.572,1.794 131.572,2.286 J2_DG5.7@132.207,2.286 132.969,2.286 133.477,2.794 133.477,2.896 134.036,3.454 v1(135.535,3.454) ; v1(94.463,9.931) 95.733,11.201 104.166,11.201 104.767,11.802 v1(106.045,13.081) ; v1(137.948,17.602) 139.7,17.602 140.589,16.713 140.589,15.57 139.577,14.558 U1.57@139.577,11.273 ; v1(171.501,7.137) 174.93,7.137 175.972,6.096 246.279,6.096 v1(246.507,5.867) 250.14,5.867 250.698,6.426 295.021,6.426 296.114,5.334 296.114,1.27 295.555,0.711 289.433,0.711 288.087,2.057 288.087,2.946 287.808,3.226 285.547,3.226 J2_DG1.7@284.607,2.286 ; J2_DG3.7@208.407,2.286 210.643,0.051 245.542,0.051 246.507,1.016 J2_DG2.7@246.507,2.286
  Bottom Layer w0.2: J2_DG6.7@94.107,2.286 94.107,9.576 v1(94.463,9.931) ; v1(106.045,13.081) 113.386,20.422 129.54,20.422 132.741,17.221 137.567,17.221 v1(137.948,17.602) ; v1(135.535,3.454) 136.652,4.572 137.433,5.353 143.637,5.353 144.888,4.102 152.253,4.102 153.504,5.353 154.241,5.353 155.289,6.401 170.18,6.401 170.307,6.273 J2_DG4.7@170.307,2.286 ; 170.307,5.715 171.069,5.715 171.501,6.147 v1(171.501,7.137) ; J2_DG2.7@246.507,2.286 v1(246.507,5.867)
RED1: J2_DG1.8 J2_DG2.8 J2_DG3.8 J2_DG4.8 J2_DG5.8 J2_DG6.8 J2_DG7.8 J2_DG8.8 U1.59 | length 355.7
  Top Layer w0.2: v1(25.096,8.788) 25.553,8.331 96.978,8.331 97.232,8.585 109.22,8.585 v1(109.703,9.068) ; v1(63.246,7.976) 63.602,8.331 ; J2_DG5.8@134.747,2.286 135.814,2.286 137.16,0.94 161.417,0.94 161.748,1.27 161.748,2.743 162.23,3.226 166.37,3.226 166.828,2.769 166.828,1.499 167.386,0.94 171.501,0.94 J2_DG4.8@172.847,2.286 174.041,1.092 v1(176.073,1.092) ; U1.59@140.577,11.273 140.577,12.383 v1(140.894,12.7) ; J2_DG3.8@210.947,2.286 210.947,0.94 211.405,0.483 245.136,0.483 245.568,0.914 245.568,2.896 245.898,3.226 247.168,3.226 248.108,2.286 J2_DG2.8@249.047,2.286 249.047,1.27 250.241,0.076 284.938,0.076 J2_DG1.8@287.147,2.286
  Bottom Layer w0.2: J2_DG8.8@20.447,2.286 20.447,4.14 v1(25.096,8.788) ; J2_DG7.8@58.547,2.286 59.487,1.346 61.697,1.346 62.027,1.676 62.027,6.756 v1(63.246,7.976) ; J2_DG6.8@96.647,2.286 96.647,7.747 v1(97.486,8.585) ; J2_DG5.8@134.747,2.286 134.747,4.445 133.731,5.461 128.245,5.461 125.603,8.103 114.173,8.103 113.564,7.493 110.871,7.493 110.568,7.796 110.568,8.203 v1(109.703,9.068) 111.989,9.068 122.073,19.152 125.476,19.152 126.289,18.339 126.289,13.36 126.823,12.827 129.871,12.827 131.008,11.69 131.033,11.715 133.192,11.715 136.373,8.534 139.878,8.534 140.513,9.169 140.513,12.319 v1(140.894,12.7) ; v1(176.073,1.092) 176.632,0.533 198.4,0.533 199.39,1.524 199.39,2.591 200.025,3.226 210.008,3.226 J2_DG3.8@210.947,2.286
RED2: J2_DG1.9 J2_DG2.9 J2_DG3.9 J2_DG4.9 J2_DG5.9 J2_DG6.9 J2_DG7.9 J2_DG8.9 U1.60 | length 375.3
  Top Layer w0.2: v1(62.307,9.982) 62.307,9.804 62.586,9.525 63.602,9.525 63.958,9.169 96.139,9.169 97.765,10.795 100.915,10.795 ; J2_DG6.9@99.187,2.286 100.108,1.365 100.68,1.365 101.105,0.94 129.744,0.94 130.607,1.803 130.607,2.896 131.572,3.861 134.595,3.861 134.951,4.216 136.17,4.216 136.297,4.089 136.297,3.175 136.703,2.769 136.703,2.286 J2_DG5.9@137.287,2.286 ; v1(100.051,9.931) 100.915,10.795 ; U1.60@141.077,11.273 141.077,10.267 140.589,9.779 136.163,9.779 134.563,11.379 131.217,11.379 130.404,12.192 106.807,12.192 105.41,10.795 100.915,10.795 ; v1(143.002,3.962) 143.561,3.404 155.727,3.404 156.083,3.048 156.083,1.778 156.515,1.346 161.138,1.346 161.341,1.549 161.341,2.903 162.064,3.626 167.926,3.626 168.326,3.226 174.448,3.226 J2_DG4.9@175.387,2.286 ; v1(251.587,5.664) 294.894,5.664 295.707,4.851 295.707,1.524 295.529,1.346 290.627,1.346 J2_DG1.9@289.687,2.286
  Bottom Layer w0.2: J2_DG8.9@22.987,2.286 22.657,2.286 22.657,4.115 23.14,4.597 26.239,4.597 26.899,3.937 46.406,3.937 47.422,2.921 47.422,1.549 47.625,1.346 56.566,1.346 57.1,1.88 57.1,4.775 61.087,8.763 ; J2_DG7.9@61.087,2.286 61.087,8.763 ; v1(62.307,9.982) 61.087,8.763 ; J2_DG6.9@99.187,2.286 99.187,6.858 99.492,7.163 99.492,9.373 v1(100.051,9.931) ; J2_DG5.9@137.287,2.286 137.948,2.286 139.624,3.962 v1(143.002,3.962) ; J2_DG4.9@175.387,2.286 176.403,2.286 176.784,1.905 176.784,1.55 177.394,0.94 196.165,0.94 197.308,2.083 197.308,2.972 197.993,3.658 212.116,3.658 214.427,1.346 217.094,1.346 217.628,1.88 217.628,5.791 218.72,6.883 250.419,6.883 251.587,5.715 J2_DG2.9@251.587,2.286
RED3: J2_DG1.10 J2_DG2.10 J2_DG3.10 J2_DG4.10 J2_DG5.10 J2_DG6.10 J2_DG7.10 J2_DG8.10 U1.61 | length 339.2
  Top Layer w0.2: J2_DG8.10@25.527,2.286 26.467,1.346 31.212,1.346 31.547,1.681 31.547,2.54 32.639,3.632 62.281,3.632 J2_DG7.10@63.627,2.286 ; v1(73.229,3.556) 73.711,4.039 88.926,4.039 89.332,3.632 100.381,3.632 J2_DG6.10@101.727,2.286 ; v1(114.834,6.858) 117.069,9.093 130.709,9.093 v1(131.649,10.033) ; v1(141.351,9.296) 141.577,9.522 U1.61@141.577,11.273 ; v1(160.122,3.581) 160.566,4.026 169.368,4.026 169.761,3.632 176.581,3.632 J2_DG4.10@177.927,2.286
  Bottom Layer w0.2: J2_DG7.10@63.627,2.286 64.897,3.556 v1(73.229,3.556) ; J2_DG6.10@101.727,2.286 101.727,10.414 102.108,10.795 105.283,10.795 105.461,10.617 105.461,6.477 106.553,5.385 113.361,5.385 113.615,5.639 113.869,5.385 115.748,7.264 ; v1(114.834,6.858) 115.24,7.264 124.613,7.264 127.381,4.496 131.903,4.496 132.538,3.861 133.376,3.861 133.808,3.429 133.808,1.524 133.985,1.346 138.888,1.346 J2_DG5.10@139.827,2.286 140.767,1.346 158.318,1.346 159.131,2.159 159.131,2.851 159.258,2.978 159.518,2.978 v1(160.122,3.581) ; v1(131.649,10.033) 134.112,10.033 136.017,8.128 140.183,8.128 v1(141.351,9.296) ; J2_DG4.10@177.927,2.286 178.588,2.286 179.528,1.346 193.929,1.346 194.539,1.956 194.539,5.029 195.149,5.639 215.977,5.639 ; J2_DG3.10@216.027,2.286 216.027,6.223 217.094,7.29 252.984,7.29 254.127,6.147 J2_DG2.10@254.127,2.286 ; 254.127,3.226 256.921,6.02 289.459,6.02 292.227,3.251 J2_DG1.10@292.227,2.286
RED4: J2_DG1.11 J2_DG2.11 J2_DG3.11 J2_DG4.11 J2_DG5.11 J2_DG6.11 J2_DG7.11 J2_DG8.11 U1.63 | length 348.8
  Top Layer w0.2: J2_DG8.11@28.067,2.286 29.922,4.14 64.313,4.14 J2_DG7.11@66.167,2.286 68.453,4.572 89.18,4.572 89.535,4.216 100.635,4.216 100.889,3.962 101.677,3.962 103.353,2.286 J2_DG6.11@104.267,2.286 105.207,3.226 118.237,3.226 118.669,3.658 123.394,3.658 123.775,4.039 127.331,4.039 129.065,5.773 137.229,5.773 139.142,3.861 140.132,3.861 141.707,2.286 J2_DG5.11@142.367,2.286 ; v1(104.267,9.906) 108.191,9.906 109.664,11.379 128.423,11.379 v1(129.134,10.668) ; U1.63@142.577,11.273 142.577,10.16 143.136,9.601 v1(152.4,9.601) ; 158.471,4.42 158.477,4.426 170.333,4.426 170.72,4.039 178.715,4.039 J2_DG4.11@180.467,2.286 ; v1(190.399,3.912) 190.627,3.683 196.469,3.683 196.876,4.089 216.764,4.089 J2_DG3.11@218.567,2.286 220.32,4.039 241.097,4.039 241.554,4.496 254.458,4.496 J2_DG2.11@256.667,2.286 258.014,3.632 292.685,3.632 294.031,2.286 J2_DG1.11@294.767,2.286
  Bottom Layer w0.2: J2_DG6.11@104.267,2.286 v1(104.267,9.906) ; v1(129.134,10.668) 130.785,9.017 134.48,9.017 135.776,7.722 140.539,7.722 140.843,8.026 141.859,8.026 142.85,9.017 151.816,9.017 v1(152.4,9.601) ; J2_DG5.11@142.367,2.286 143.129,2.286 144.145,3.302 152.781,3.302 153.035,3.556 156.21,3.556 157.074,4.42 v1(157.988,4.42) ; J2_DG4.11@180.467,2.286 182.093,3.912 v1(190.399,3.912)
ROWA0: J1_DG1.4 U1.115 | length 145.6
  Top Layer w0.2: U1.115@165.227,18.423 166.303,18.423 168.961,21.082 v1(169.012,21.082) ; v1(177.902,28.016) 178.62,28.734 214.129,28.734 233.096,47.701 277.952,47.701 280.797,50.546 280.797,51.943 281.356,52.502 293.828,52.502 J1_DG1.4@294.767,51.562
  Bottom Layer w0.2: v1(169.012,21.082) 169.012,21.133 170.892,23.012 174.041,23.012 177.902,26.873 v1(177.902,28.016)
ROWA1: J1_DG1.5 U1.121 | length 144.8
  Top Layer w0.2: U1.121@165.227,21.423 168.25,21.423 172.696,25.869 174.943,25.869 175.159,25.654 179.922,25.654 180.989,26.721 191.32,26.721 191.853,26.187 253.315,26.187 269.698,42.57 291.262,42.57 292.227,43.536 J1_DG1.5@292.227,51.562
ROWA2: J1_DG1.6 U1.122 | length 141.3
  Top Layer w0.2: U1.122@165.227,21.923 168.075,21.923 172.421,26.269 175.54,26.269 175.749,26.06 179.522,26.06 180.589,27.127 240.284,27.127 256.21,43.053 288.621,43.053 289.687,44.12 J1_DG1.6@289.687,51.562
ROWA3: J1_DG1.7 U1.123 | length 138.3
  Top Layer w0.2: U1.123@165.227,22.423 167.437,22.423 171.684,26.67 175.736,26.67 175.94,26.466 179.121,26.466 180.189,27.534 233.851,27.534 249.93,43.612 286.182,43.612 287.147,44.577 J1_DG1.7@287.147,51.562
ROWA4: J1_DG1.8 U1.125 | length 132.3
  Top Layer w0.2: U1.125@165.227,23.423 167.818,23.423 171.471,27.076 176.353,27.076 176.563,26.866 178.715,26.866 179.783,27.934 229.458,27.934 245.796,44.272 279.095,44.272 284.607,49.784 J1_DG1.8@284.607,51.562
ROWA5: J1_DG1.9 U1.127 | length 129.3
  Top Layer w0.2: U1.127@165.227,24.423 168.225,24.423 171.284,27.483 176.517,27.483 176.734,27.266 178.258,27.266 179.325,28.334 229.096,28.334 245.822,45.06 277.343,45.06 282.067,49.784 J1_DG1.9@282.067,51.562
ROWA6: J1_DG1.10 U1.129 | length 125.1
  Top Layer w0.2: U1.129@165.227,25.423 168.654,25.423 171.146,27.915 175.819,27.915 177.039,29.134 205.207,29.134 224.181,48.108 276.073,48.108 J1_DG1.10@279.527,51.562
